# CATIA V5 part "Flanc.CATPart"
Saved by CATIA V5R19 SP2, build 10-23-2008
Part number: Flanc
Bounding box of the stored display mesh (mm): x 0 to 1, y -8 to 81.301, z -11.357 to 7.117
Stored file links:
  G:\EU_thinkMotion\CFAO_2010\MMS_groupe3\MMS_groupe3\A reprendre\lletoffe\lletoffe_Thinkmotion_CFAO\Modèle Catia\Flanc.CATPart
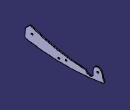
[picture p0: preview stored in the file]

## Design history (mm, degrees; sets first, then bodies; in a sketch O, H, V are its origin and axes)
Parameters
  Epaisseur_Flanc = 1 mm
Set1
  Point1: (0, 30.2, -8.3)
  Point2: (1, 30.2, -8.3)
  Line1: type PtPt, FirstPoint Point1, SecondPoint Point2, Start 10, End 10
  Point3: (1, 38.5, -6.2)
  Point4: (0, 38.5, -6.2)
  Line2: type PtPt, FirstPoint Point3, SecondPoint Point4, Start 10, End 10
  Point5: (0, 0, 0)
  Point6: (1, 0, 0)
  Line3: type PtPt, FirstPoint Point5, SecondPoint Point6, Start 10, End 10
  Point7: (1, 74, 0)
  Point8: (0, 74, 0)
  Line4: type PtPt, FirstPoint Point7, SecondPoint Point8, Start 10, End 10
  Plane1: type Offset, RefPlane yz-plane, Offset 1 {= Epaisseur_Flanc}
  Sketch1 on yz-plane, origin (0, 0, 0), H (0, 1, 0), V (0, 0, 1)
    circle A1 centre (0, 0) radius 1
    arc A2 centre (37, -5.898) radius 45 from (-7.2161, 2.4646) to (-7.9998, -6.0473) ccw
    arc A3 centre (-6.2498, -6.0414) radius 1.75 from (-7.9998, -6.0473) to (-6.5511, -7.7653) ccw
    arc A4 centre (36.5, 238.5) radius 250 from (-6.5511, -7.7653) to (80.0621, -7.6754) ccw
    arc A5 centre (-4.7597, 2) radius 2.5 from (-5.5982, 4.3552) to (-7.2161, 2.4646) ccw
    arc A6 centre (-2, 5.2322) radius 2 from (-1.3321, 7.1174) to (-3.8418, 6.0119) ccw
    point P1 (-2, 5.2322)
    construction line L1 through (0, 0.2458) direction (0, 1)
    arc A7 centre (67, 200) radius 204.6289 from (-1.3321, 7.1174) to (60.2357, -4.5171) ccw
    point P2 (-1.3321, 7.1174)
    construction line L2 through (-0.8305, 0) direction (1, 0)
    point P3 (67, 200)
    arc A8 centre (-6.6044, 7.1814) radius 3 from (-5.5982, 4.3552) to (-3.8418, 6.0119) ccw
    arc A9 centre (65, -3) radius 5 from (60.2357, -4.5171) to (68.3333, -6.7268) ccw
    arc A10 centre (67, -5.2361) radius 2 from (68.3333, -6.7268) to (69, -5.2361) ccw
    line L3 (69, 0) -> (69, -5.2361)
    point P4 (65, -3)
    circle A11 centre (30.2, -8.3) radius 1
    point P5 (-1.3321, 7.1174)
    point P6 (-1.3321, 7.1174)
    point P7 (36.5, 238.5)
    arc A12 centre (74, 0) radius 5 from (79, 0) to (69, 0) ccw
    arc A13 centre (79.8007, -6.1984) radius 1.5 from (80.9374, -5.2197) to (80.0621, -7.6754) cw
    circle A14 centre (38.5, -6.2) radius 1
    point P8 (38.5, -6.2)
    point P9 (30.2, -8.3)
    point P10 (74, 0)
    point P11 (80.0621, -7.6754)
    point P12 (80.0621, -7.6754)
    point P13 (37, -5.898)
    point P14 (-6.2498, -6.0414)
    point P15 (-4.7597, 2)
    point P16 (79, 0)
    point P17 (79, 0)
    arc A15 centre (87, 0) radius 8 from (79, 0) to (80.9374, -5.2197) ccw
    point P18 (80.9374, -5.2197)
    point P19 (80.9374, -5.2197)
    point P20 (87, 0)
    circle A16 centre (74, 0) radius 1
    point P23 (79.001, -0.0987)
    point P27 (37, -5.9535)
    point P28 (37, -11.5)
    point P29 (28.2291, -7.9598)
    point P30 (32.1934, -8.1382)
    point P31 (51.7006, -11.5)
    point P39 (0, 0)
    reference projected point E1 (30.2, -8.3) from vertex of Line1
    reference projected point E2 (38.5, -6.2) from vertex of Line2
    reference projected point E3 (0, 0) from vertex of Line3
    radius A1 = 1
    radius A3 = 1.75
    radius A4 = 250
    radius A6 = 2
    distance L1 P1 = 2
    distance P3 L2 = 200
    radius A9 = 5
    distance P4 L2 = 3
    distance L1 P4 = 65
    radius A10 = 2
    radius A11 = 1
    distance P7 L2 = 238.5
    radius A7 = 204.6289
    distance P3 L1 = 67
    radius A2 = 45
    radius A14 = 1
    distance P8 L1 = 38.5
    distance P8 L2 = 6.2
    distance L2 P9 = 8.3
    distance P9 L1 = 30.2
    distance L3 L1 = 69
    radius A12 = 5
    radius A13 = 1.5
    distance P7 L1 = 36.5
    distance L1 P13 = 37
    distance L1 P14 = 6.2498
    radius A8 = 3
    radius A5 = 2.5
    distance P15 L2 = 2
    distance P20 L3 = 18
    radius A16 = 1
    tangency: A3 A2, A4 A3, A5 A2, A7 A6, A8 A6, A8 A5, A10 A9, L3 A10, A12 L3, A13 A4, A15 A12, A15 A13
    coincidence: A7 P2, P2 A6, A7 P5, P6 A6, P6 P5, P10 L2, P12 P11, P17 P16, P19 P18, P20 L2, E1 P9, P8 E2, P39 E3
    vertical: L3 L1
Body1 (main body)
  Pad1: profile Sketch1, direction (1, 0, 0), up to Plane1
